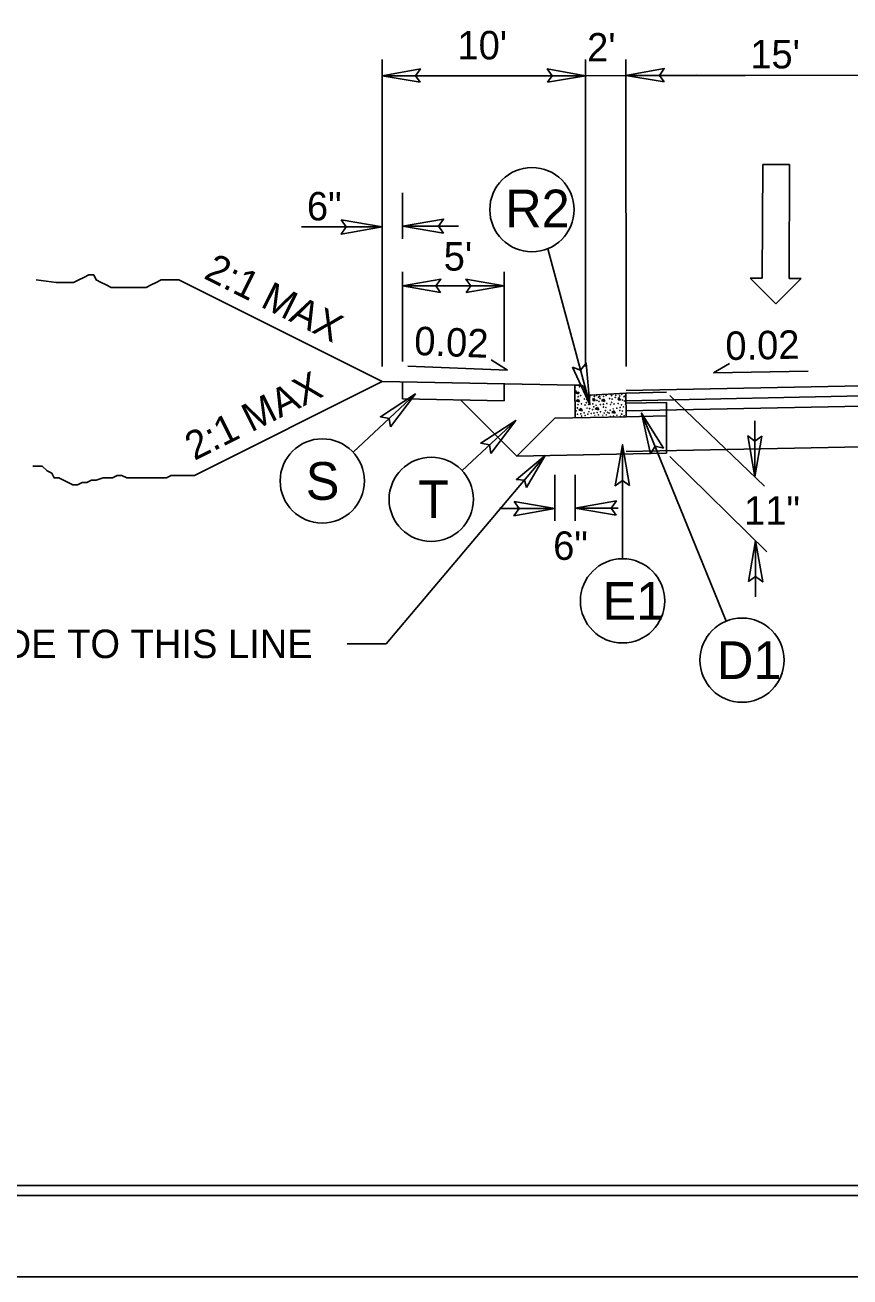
# Model space of a CAD drawing. Extents: x 1640342 to 1730599, y 538663 to 843747.
# Drawn here: x 1729967.5 to 1730008.1, y 539149.8 to 539211.3 of the extents above; entities that cross this region are included whole.
import ezdxf

# ---------------------------------------------------------------- set-up
doc = ezdxf.new("R2010")
doc.units = 0
for name, color, linetype in [('Default', 7, 'Continuous'), ('Prop Terminator CELL', 7, 'Continuous'), ('Sheet Clip Boundary CELL', 7, 'Continuous'), ('Sheet Layout Plan Border', 7, 'Continuous'), ('Sheet Plan CELL', 7, 'Continuous'), ('Sheet Plan Layout CELL', 7, 'Continuous'), ('Sheet Plot Border Inside CELL', 7, 'Continuous'), ('Sheet Plot Border Outside CELL', 7, 'Continuous'), ('Typical Curb CELL', 7, 'Continuous'), ('Typical Hinge Slope Arterial CELL', 7, 'Continuous'), ('Typical Hinge Slope Interstate CELL', 7, 'Continuous'), ('Typical ID Circle CELL', 7, 'Continuous'), ('Typical Pavement Slope CELL', 7, 'Continuous'), ('Typical Pavement Slope Information CELL', 7, 'Continuous'), ('Typical Shoulder Slope CELL', 7, 'Continuous'), ('Typical Terminator CELL', 7, 'Continuous'), ('Typical Text General CELL', 7, 'Continuous'), ('Typical Text ID Circle CELL', 7, 'Continuous')]:
    doc.layers.add(name, color=color, linetype=linetype)

msp = doc.modelspace()

# ---------------------------------------------------------------- linework, layer by layer
at = {"layer": 'Default'}
for p, q in [((1729985.075, 539194.541), (1729985.075, 539209.631)), ((1729995.075, 539194.541), (1729995.075, 539209.631)), ((1729997.068, 539194.547), (1729997.053, 539209.637)), ((1729985.075, 539208.842), (1729995.076, 539208.842)), ((1729997.054, 539208.855), (1729995.076, 539208.842)), ((1730002.913, 539208.855), (1730010.789, 539208.863)), ((1730003.754, 539198.882), (1730003.784, 539204.477)), ((1730003.784, 539204.477), (1730005.103, 539204.47)), ((1730005.103, 539204.47), (1730005.073, 539198.875)), ((1729986.075, 539203.076), (1729986.075, 539200.817)), ((1729981.106, 539201.412), (1729985.075, 539201.412)), ((1729988.825, 539201.436), (1729986.075, 539201.436)), ((1729986.075, 539194.795), (1729986.075, 539199.197)), ((1729991.075, 539194.795), (1729991.075, 539199.197)), ((1730004.427, 539197.619), (1730003.155, 539198.885)), ((1730003.155, 539198.885), (1730003.754, 539198.882)), ((1730005.673, 539198.871), (1730004.427, 539197.619)), ((1730005.073, 539198.875), (1730005.673, 539198.871)), ((1729991.075, 539198.501), (1729986.075, 539198.501)), ((1729999.212, 539193.121), (1730003.867, 539188.664)), ((1730003.398, 539191.863), (1730003.398, 539189.113)), ((1729999.212, 539190.121), (1730003.974, 539185.428)), ((1729993.567, 539189.221), (1729993.567, 539186.961)), ((1729994.567, 539189.221), (1729994.567, 539186.961)), ((1729990.836, 539187.557), (1729993.567, 539187.557)), ((1729996.667, 539187.581), (1729994.567, 539187.581)), ((1730003.422, 539183.221), (1730003.422, 539185.971))]:
    msp.add_line(p, q, dxfattribs=at)
for points in [[(1729986.949, 539208.519), (1729985.075, 539208.842), (1729986.959, 539209.175), (1729986.72, 539208.842)], [(1729993.201, 539208.519), (1729995.076, 539208.842), (1729993.191, 539209.175), (1729993.43, 539208.842)], [(1729998.928, 539208.532), (1729997.054, 539208.855), (1729998.938, 539209.188), (1729998.699, 539208.855)], [(1729987.949, 539198.178), (1729986.075, 539198.501), (1729987.959, 539198.834), (1729987.72, 539198.501)], [(1729989.2, 539198.178), (1729991.075, 539198.501), (1729989.19, 539198.834), (1729989.429, 539198.501)]]:
    msp.add_lwpolyline(points, close=True, dxfattribs=at)
msp.add_lwpolyline([(1729997.054, 539208.855), (1730002.913, 539208.855), (1730000.541, 539208.865)], dxfattribs=at)
at = {"layer": 'Prop Terminator CELL'}
msp.add_lwpolyline([(1729992.165, 539188.585), (1729993.091, 539190.16), (1729991.677, 539188.984), (1729992.07, 539188.953)], close=True, dxfattribs=at)
at = {"layer": 'Sheet Clip Boundary CELL'}
msp.add_lwpolyline([(1729883.99, 539154.279), (1730163.993, 539154.279), (1730163.993, 539321.981), (1730126.14, 539321.981), (1730126.14, 539364.279), (1729883.99, 539364.279)], close=True, dxfattribs=at)
at = {"layer": 'Sheet Layout Plan Border'}
msp.add_lwpolyline([(1729883.99, 539154.279), (1730163.993, 539154.279), (1730163.993, 539321.981), (1730126.14, 539321.981), (1730126.14, 539364.279), (1729883.99, 539364.279)], close=True, dxfattribs=at)
at = {"layer": 'Sheet Plan CELL'}
for points in [[(1729873.99, 539154.279), (1729873.985, 539364.274), (1730133.983, 539364.281), (1730133.985, 539334.269), (1730173.993, 539334.266), (1730173.993, 539154.279)], [(1730173.998, 539364.279), (1729873.99, 539364.279), (1729873.99, 539154.279), (1730173.993, 539154.279)]]:
    msp.add_lwpolyline(points, close=True, dxfattribs=at)
at = {"layer": 'Sheet Plan Layout CELL'}
msp.add_lwpolyline([(1729873.985, 539364.274), (1729873.99, 539154.279), (1730173.99, 539154.279), (1730173.99, 539321.981), (1730126.14, 539321.981), (1730126.14, 539364.279)], close=True, dxfattribs=at)
at = {"layer": 'Sheet Plot Border Inside CELL'}
msp.add_lwpolyline([(1729843.293, 539153.776), (1730176.49, 539153.779), (1730176.493, 539364.776), (1729843.293, 539364.776)], close=True, dxfattribs=at)
at = {"layer": 'Sheet Plot Border Outside CELL'}
msp.add_lwpolyline([(1729840.693, 539149.776), (1730177.393, 539149.776), (1730177.393, 539368.776), (1729840.693, 539368.776)], close=True, dxfattribs=at)
at = {"layer": 'Typical Curb CELL'}
for p, q in [((1729994.543, 539193.617), (1729994.803, 539193.621)), ((1729994.567, 539192.023), (1729994.543, 539193.617)), ((1729994.585, 539193.24), (1729994.738, 539193.287)), ((1729994.723, 539193.196), (1729994.585, 539193.24)), ((1729994.738, 539193.287), (1729994.723, 539193.196)), ((1729995.046, 539193.375), (1729995.046, 539193.385)), ((1729997.046, 539193.239), (1729995.299, 539193.139)), ((1729997.064, 539192.073), (1729997.046, 539193.239)), ((1729994.716, 539192.923), (1729994.614, 539192.847)), ((1729994.614, 539192.847), (1729994.78, 539192.81)), ((1729994.78, 539192.81), (1729994.716, 539192.923)), ((1729995.456, 539192.991), (1729995.423, 539192.877)), ((1729995.423, 539192.877), (1729995.543, 539192.872)), ((1729995.543, 539192.872), (1729995.456, 539192.991)), ((1729995.963, 539192.942), (1729995.861, 539192.866)), ((1729995.861, 539192.866), (1729996.027, 539192.829)), ((1729996.027, 539192.829), (1729995.963, 539192.942)), ((1729996.703, 539193.01), (1729996.671, 539192.896)), ((1729996.671, 539192.896), (1729996.792, 539192.892)), ((1729996.792, 539192.892), (1729996.703, 539193.01)), ((1729994.849, 539192.474), (1729994.747, 539192.397)), ((1729994.747, 539192.397), (1729994.913, 539192.36)), ((1729994.913, 539192.36), (1729994.849, 539192.474)), ((1729995.654, 539192.53), (1729995.552, 539192.454)), ((1729995.552, 539192.454), (1729995.718, 539192.417)), ((1729995.718, 539192.417), (1729995.654, 539192.53)), ((1729996.46, 539192.361), (1729996.358, 539192.285)), ((1729996.358, 539192.285), (1729996.524, 539192.248)), ((1729996.524, 539192.248), (1729996.46, 539192.361))]:
    msp.add_line(p, q, dxfattribs=at)
for centre in [(1729994.558, 539193.507), (1729994.612, 539193.325), (1729994.774, 539193.545), (1729994.702, 539192.666), (1729994.713, 539193.054), (1729994.832, 539193.106), (1729994.872, 539192.708), (1729995.011, 539192.944), (1729995.05, 539192.648), (1729995.088, 539193.139), (1729995.105, 539192.763), (1729995.106, 539193.089), (1729995.137, 539192.918), (1729995.221, 539192.68), (1729995.284, 539193.006), (1729995.311, 539193.108), (1729995.426, 539192.706), (1729995.506, 539193.072), (1729995.586, 539192.64), (1729995.602, 539193.127), (1729995.634, 539192.874), (1729995.712, 539193.035), (1729995.731, 539192.83), (1729995.767, 539193.07), (1729995.786, 539192.974), (1729995.796, 539192.666), (1729995.95, 539192.685), (1729995.961, 539193.073), (1729996.08, 539193.126), (1729996.12, 539192.728), (1729996.259, 539192.964), (1729996.298, 539192.668), (1729996.336, 539193.158), (1729996.353, 539192.783), (1729996.354, 539193.108), (1729996.385, 539192.937), (1729996.469, 539192.699), (1729996.532, 539193.025), (1729996.559, 539193.127), (1729996.674, 539192.725), (1729996.706, 539193.192), (1729996.754, 539193.091), (1729996.834, 539192.659), (1729996.849, 539193.177), (1729996.882, 539192.893), (1729996.96, 539193.054), (1729996.979, 539192.849), (1729997.015, 539193.089), (1729997.034, 539192.993), (1729997.044, 539192.685), (1729994.616, 539192.362), (1729994.671, 539192.505), (1729994.681, 539192.197), (1729994.835, 539192.217), (1729994.881, 539192.105), (1729995.006, 539192.259), (1729995.052, 539192.136), (1729995.144, 539192.495), (1729995.183, 539192.199), (1729995.239, 539192.314), (1729995.27, 539192.469), (1729995.354, 539192.23), (1729995.422, 539192.418), (1729995.476, 539192.561), (1729995.487, 539192.253), (1729995.537, 539192.133), (1729995.641, 539192.273), (1729995.708, 539192.164), (1729995.811, 539192.315), (1729995.921, 539192.133), (1729995.95, 539192.551), (1729995.989, 539192.255), (1729996.044, 539192.37), (1729996.076, 539192.525), (1729996.092, 539192.164), (1729996.16, 539192.287), (1729996.227, 539192.249), (1729996.282, 539192.393), (1729996.293, 539192.085), (1729996.436, 539192.461), (1729996.446, 539192.104), (1729996.607, 539192.492), (1729996.617, 539192.147), (1729996.756, 539192.383), (1729996.774, 539192.527), (1729996.795, 539192.087), (1729996.85, 539192.202), (1729996.882, 539192.356), (1729996.944, 539192.558), (1729996.965, 539192.118)]:
    msp.add_circle(centre, 0.00801, dxfattribs=at)
for centre, start, end in [((1729994.806, 539193.381), 0.8814, 90.8814), ((1729995.285, 539193.378), 180.8814, 273.26586)]:
    msp.add_arc(centre, 0.239, start, end, dxfattribs=at)
at = {"layer": 'Typical Hinge Slope Arterial CELL'}
for p, q in [((1729975.082, 539198.802), (1729985.075, 539193.806)), ((1729985.075, 539193.806), (1729975.858, 539189.183))]:
    msp.add_line(p, q, dxfattribs=at)
msp.add_lwpolyline([(1729968.065, 539198.802), (1729969.049, 539198.68), (1729969.295, 539198.68), (1729969.665, 539198.68), (1729969.911, 539198.68), (1729970.158, 539198.802), (1729970.404, 539198.926), (1729970.65, 539199.05), (1729970.896, 539199.05), (1729971.02, 539198.802), (1729971.266, 539198.68), (1729971.512, 539198.556), (1729971.758, 539198.434), (1729972.004, 539198.434), (1729972.251, 539198.434), (1729972.497, 539198.434), (1729972.743, 539198.434), (1729972.989, 539198.434), (1729973.235, 539198.434), (1729973.482, 539198.434), (1729973.728, 539198.556), (1729973.974, 539198.68), (1729974.22, 539198.802), (1729974.59, 539198.802), (1729974.836, 539198.802), (1729975.082, 539198.802)], dxfattribs=at)
at = {"layer": 'Typical Hinge Slope Interstate CELL'}
msp.add_lwpolyline([(1729967.91, 539189.644), (1729968.14, 539189.644), (1729968.37, 539189.644), (1729968.601, 539189.413), (1729968.831, 539189.298), (1729968.947, 539189.067), (1729969.177, 539189.067), (1729969.407, 539188.953), (1729969.638, 539188.837), (1729969.868, 539188.722), (1729970.098, 539188.722), (1729970.329, 539188.837), (1729970.559, 539188.837), (1729970.789, 539188.953), (1729971.02, 539188.953), (1729971.366, 539189.067), (1729971.596, 539189.067), (1729971.826, 539189.067), (1729972.057, 539189.183), (1729972.287, 539189.183), (1729972.517, 539189.067), (1729972.748, 539189.067), (1729972.978, 539189.067), (1729973.208, 539189.067), (1729973.439, 539189.067), (1729973.785, 539189.067), (1729974.13, 539189.067), (1729974.476, 539189.067), (1729974.706, 539189.183), (1729975.051, 539189.183), (1729975.397, 539189.183), (1729975.858, 539189.183)], dxfattribs=at)
at = {"layer": 'Typical ID Circle CELL'}
for p, q in [((1729993.218, 539200.336), (1729995.29, 539192.669)), ((1729983.645, 539190.33), (1729986.709, 539193.191)), ((1730001.985, 539182.022), (1729997.828, 539192.254)), ((1729989, 539189.426), (1729991.639, 539191.89)), ((1729996.89, 539185.09), (1729996.89, 539190.699))]:
    msp.add_line(p, q, dxfattribs=at)
for centre in [(1729992.436, 539202.253), (1729982.131, 539188.916), (1729987.487, 539188.012), (1729996.89, 539183.019), (1730002.764, 539180.103)]:
    msp.add_circle(centre, 2.071, dxfattribs=at)
at = {"layer": 'Typical Pavement Slope CELL'}
for p, q in [((1729997.069, 539193.362), (1730020.913, 539193.839)), ((1729997.046, 539193.239), (1729999.046, 539193.279)), ((1729997.07, 539192.862), (1730020.913, 539193.338)), ((1729988.932, 539192.896), (1729991.696, 539190.132)), ((1729997.056, 539192.739), (1729999.056, 539192.779)), ((1729997.07, 539192.361), (1730020.923, 539192.839)), ((1729999.046, 539192.279), (1729999.046, 539192.779)), ((1729993.567, 539192.003), (1729991.696, 539190.132)), ((1729993.567, 539192.003), (1729997.064, 539192.073)), ((1729997.064, 539192.073), (1729999.046, 539192.113)), ((1729997.072, 539190.362), (1730020.913, 539190.839)), ((1729991.696, 539190.132), (1729999.046, 539190.279))]:
    msp.add_line(p, q, dxfattribs=at)
msp.add_lwpolyline([(1729999.046, 539192.279), (1729999.046, 539190.279)], dxfattribs=at)
at = {"layer": 'Typical Pavement Slope Information CELL'}
for p, q in [((1729991.239, 539194.354), (1729986.34, 539194.551)), ((1729991.239, 539194.354), (1729990.426, 539194.868)), ((1730001.359, 539194.223), (1730002.142, 539194.696)), ((1730001.359, 539194.223), (1730006.018, 539194.316))]:
    msp.add_line(p, q, dxfattribs=at)
at = {"layer": 'Typical Shoulder Slope CELL'}
for p, q in [((1729985.075, 539193.806), (1729994.543, 539193.617)), ((1729986.075, 539192.953), (1729986.075, 539193.787)), ((1729991.075, 539193.687), (1729991.075, 539192.853)), ((1729986.075, 539192.953), (1729991.075, 539192.853))]:
    msp.add_line(p, q, dxfattribs=at)
at = {"layer": 'Typical Terminator CELL'}
for p, q in [((1729985.265, 539180.906), (1729993.091, 539190.16)), ((1729983.356, 539180.906), (1729985.265, 539180.906))]:
    msp.add_line(p, q, dxfattribs=at)
for points in [[(1729983.067, 539201.758), (1729985.075, 539201.412), (1729983.056, 539201.055), (1729983.312, 539201.412)], [(1729988.082, 539201.09), (1729986.075, 539201.436), (1729988.094, 539201.793), (1729987.837, 539201.436)], [(1729994.432, 539194.517), (1729995.29, 539192.669), (1729995.108, 539194.711), (1729994.83, 539194.37)], [(1729985.477, 539191.568), (1729986.709, 539193.191), (1729984.99, 539192.074), (1729985.421, 539191.988)], [(1729998.904, 539190.524), (1729997.828, 539192.254), (1729998.257, 539190.25), (1729998.491, 539190.622)], [(1729990.408, 539190.267), (1729991.639, 539191.89), (1729989.92, 539190.773), (1729990.351, 539190.687)], [(1730003.744, 539191.12), (1730003.398, 539189.113), (1730003.041, 539191.132), (1730003.398, 539190.875)], [(1729997.236, 539188.692), (1729996.89, 539190.699), (1729996.533, 539188.68), (1729996.89, 539188.937)], [(1729991.559, 539187.903), (1729993.567, 539187.557), (1729991.548, 539187.2), (1729991.805, 539187.557)], [(1729996.575, 539187.235), (1729994.567, 539187.581), (1729996.586, 539187.937), (1729996.329, 539187.581)], [(1730003.076, 539183.964), (1730003.422, 539185.971), (1730003.779, 539183.952), (1730003.422, 539184.209)]]:
    msp.add_lwpolyline(points, close=True, dxfattribs=at)

# ---------------------------------------------------------------- texts
at = {"layer": 'Default'}
for s, p in [("10'", (1729988.776, 539209.642)), ('6"', (1729981.376, 539201.724)), ('11"', (1730002.865, 539186.762)), ('6"', (1729993.479, 539185.035))]:
    msp.add_text(s, height=1.4, dxfattribs=at).set_placement(p)
msp.add_text("5'", height=1.4, rotation=360, dxfattribs=at).set_placement((1729988.099, 539199.257))
at = {"layer": 'Typical Hinge Slope Interstate CELL'}
for rotation, p in [(333.43542, (1729976.251, 539198.905)), (26.56458, (1729975.842, 539189.894))]:
    msp.add_text('2:1 MAX', height=1.4, rotation=rotation, dxfattribs=at).set_placement(p)
at = {"layer": 'Typical Pavement Slope Information CELL'}
for s, p in [("2'", (1729995.149, 539209.539)), ("15'", (1730003.168, 539209.2))]:
    msp.add_text(s, height=1.4, dxfattribs=at).set_placement(p)
for rotation, p in [(357.69972, (1729986.63, 539195.113)), (1.14574, (1730001.958, 539194.857))]:
    msp.add_text('0.02', height=1.4, rotation=rotation, dxfattribs=at).set_placement(p)
at = {"layer": 'Typical Text General CELL'}
msp.add_text('GRADE TO THIS LINE', height=1.4, dxfattribs=at).set_placement((1729962.413, 539180.206))
at = {"layer": 'Typical Text ID Circle CELL'}
for s, height, p in [('R2', 1.8535, (1729991.124, 539201.384)), ('S', 1.854, (1729981.32, 539187.989)), ('T', 1.854, (1729986.844, 539187.086)), ('E1', 1.8535, (1729995.906, 539182.092)), ('D1', 1.8535, (1730001.529, 539179.176))]:
    msp.add_text(s, height=height, dxfattribs=at).set_placement(p)

doc.saveas('drawing.dxf')
